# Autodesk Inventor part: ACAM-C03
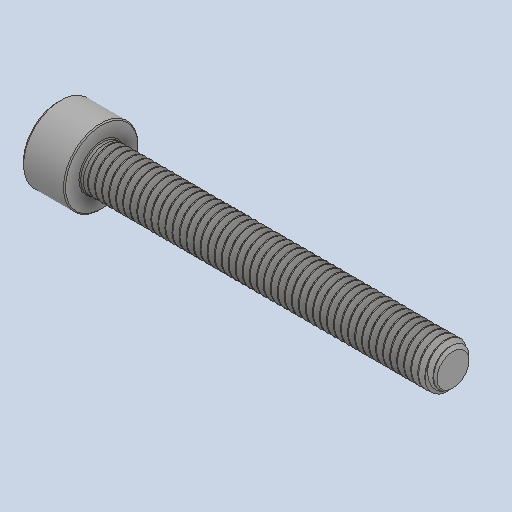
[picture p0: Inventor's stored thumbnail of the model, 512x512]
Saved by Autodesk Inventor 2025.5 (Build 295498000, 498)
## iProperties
Created: 2025-07
Part Number: ACAM-C03
Material: Genérico
Description: Tornillo Allen M5×40
Document SubType Name: Modeling
Designer: Luis M
Density: 1 g/cm^3
Appearance: Valor por defecto
Sending System: SolidWorks 2022
Preprocessor: SwSTEP 2.0
Material_BOM: Por especificar
Proceso_BOM: Comercial
Title: TORNILLO ALLEN CABEZA HEXAGONAL M5-0.8-40.STEP
Revision Number: ANY
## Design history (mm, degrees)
feature "Revolución2"
node "Sólido1"
